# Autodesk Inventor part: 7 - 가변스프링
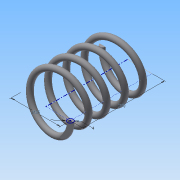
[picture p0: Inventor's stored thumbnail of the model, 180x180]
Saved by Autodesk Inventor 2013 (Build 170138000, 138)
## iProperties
Created: 2015-03
Part Number: 7 - 가변스프링
Material: 강철, 탄소
Document SubType Name: Modeling
Designer: Administrator
Density: 7.87 g/cm^3
Mass: 48.2733 g
Surface Area: 62.0009 cm^2
Volume: 6.13384 cm^3
Author: Administrator
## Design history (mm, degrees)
sketch "스케치1"
  geometry: L1 (0, 0)-(17.5, 0); L2 (17.5, 0)-(17.5, 43.5); L3 (17.5, 43.5)-(0, 43.5); L4 (0, 43.5)-(0, 0); C1 r 2 at (17.5, 0)
  constraints: 8 end point, 2 parallel, 1 centre point, 1 coincident, 1 horizontal, 1 perpendicular
  dimensions: "d0" = 4 diameter of C1; "d2" = 35 diameter of L2 L4; "d3" = 43.5 distance of L1.end L2.end (derived)
feature "코일1" pitch "d4" = 10; turns "d6" = 4.5; dims "d5" = 43.5 (= d3), "d7" = 0, angle "d8" = 90 deg, angle "d9" = 90 deg, "d10" = 0, "d11" = 0
node "작업 평면1"
sketch "스케치2"
  geometry: L1 (-19.5, 0)-(-15.5, 0) reference; 1 further point
  constraints: 1 horizontal alignment
extrude "돌출1" cut sketch "스케치2" stored distance "d13" = 10; taper "d14" = 0 deg
node "작업 평면2"
sketch "스케치3"
  geometry: L1 (-19.5, 0)-(-15.5, 0) reference; 1 further point
  constraints: 1 horizontal alignment
extrude "돌출2" cut sketch "스케치3" stored distance "d16" = 10; taper "d17" = 0 deg
node "솔리드1"
node "절단 모서리 투영1"
node "절단 모서리 투영2"
other parameters: "d12" = 0, "d15" = -43.5 (= -d3)
